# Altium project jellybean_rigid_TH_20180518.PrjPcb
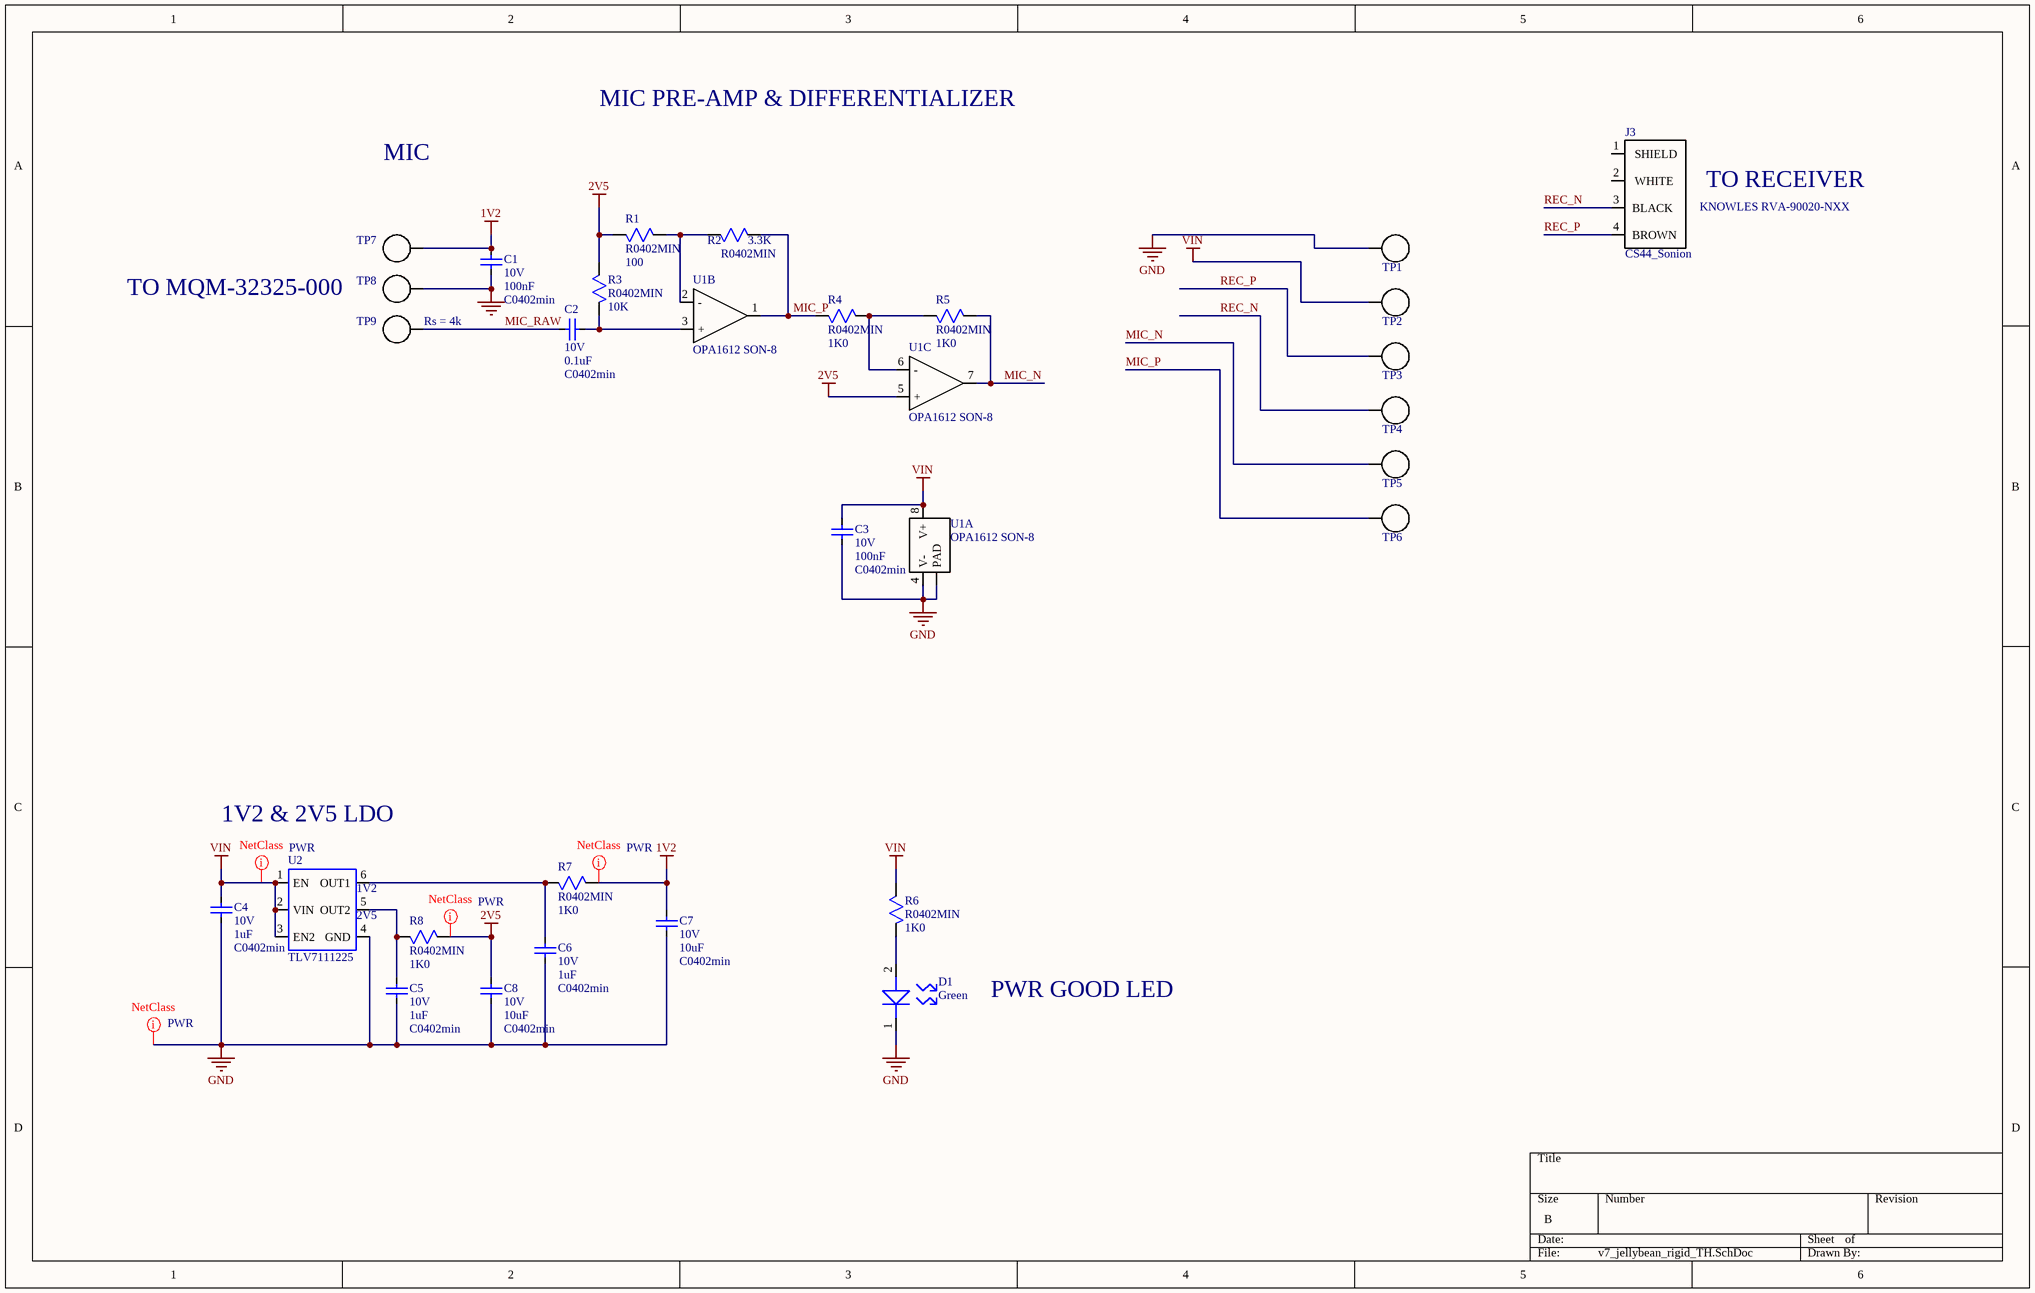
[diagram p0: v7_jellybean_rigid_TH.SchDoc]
1 sheet, 29 parts. Net scope: global (net labels, ports and power ports of the same name join across sheets).
Board file: v7_jellybean_rigid_TH.PcbDoc

## Sheet v7_jellybean_rigid_TH.SchDoc
size B

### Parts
C1  VoltageRating: 10V  [C0402min]  (hidden comment: 100nF)
C2  VoltageRating: 10V  [C0402min]  (hidden comment: 0.1uF)
C3  VoltageRating: 10V  [C0402min]  (hidden comment: 100nF)
C4  VoltageRating: 10V  [C0402min]  (hidden comment: 1uF)
C5  VoltageRating: 10V  [C0402min]  (hidden comment: 1uF)
C6  VoltageRating: 10V  [C0402min]  (hidden comment: 1uF)
C7  VoltageRating: 10V  [C0402min]  (hidden comment: 10uF)
C8  VoltageRating: 10V  [C0402min]  (hidden comment: 10uF)
D1  Color: Green  [LED0402min]  (hidden comment: LED, green)
J3  CS44_Sonion  [CS44_SOCKET_TH - EDGE - SONION]
R1  value 100  [R0402MIN]  (hidden comment: Resistor)
R2  value 3.3K  [R0402MIN]  (hidden comment: Resistor)
R3  value 10K  [R0402MIN]  (hidden comment: Resistor)
R4  value 1K0  [R0402MIN]  (hidden comment: Resistor)
R5  value 1K0  [R0402MIN]  (hidden comment: Resistor)
R6  value 1K0  [R0402MIN]  (hidden comment: Resistor)
R7  value 1K0  [R0402MIN]  (hidden comment: Resistor)
R8  value 1K0  [R0402MIN]  (hidden comment: Resistor)
TP1  Not A Part  [TP_32AWG]  (value not drawn)
TP2  Not A Part  [TP_32AWG]  (value not drawn)
TP3  Not A Part  [TP_32AWG]  (value not drawn)
TP4  Not A Part  [TP_32AWG]  (value not drawn)
TP5  Not A Part  [TP_32AWG]  (value not drawn)
TP6  Not A Part  [TP_32AWG]  (value not drawn)
TP7  Not A Part  [TP_32AWG]  (value not drawn)
TP8  Not A Part  [TP_32AWG]  (value not drawn)
TP9  Not A Part  [TP_32AWG]  (value not drawn)
U1  OPA1612 SON-8  [SON-8]  (parts A,B,C of 3)
U2  TLV7111225  [TLV711x]

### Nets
1V2: C1.1 C7.2 R7.2 TP7.1(MTG)
2V5: C8.1 R1.2 R3.2 R8.2 U1.5(+)
GND: C1.2 C3.1 C4.2 C5.2 C6.2 C7.1 C8.2 D1.1 TP1.1(MTG) TP8.1(MTG) U1.4(V-) U1.PAD U2.4(GND)
VIN: C3.2 C4.1 R6.2 TP2.1(MTG) U1.8(V+) U2.1(EN) U2.2(VIN) U2.3(EN2)
MIC_N: R5.2 TP5.1(MTG) U1.7
MIC_P: R2.2 R4.1 TP6.1(MTG) U1.1
MIC_RAW: C2.1 TP9.1(MTG)
REC_N: J3.3(BLACK) TP4.1(MTG)
REC_P: J3.4(BROWN) TP3.1(MTG)
NetC2_2: C2.2 R3.1 U1.3(+)
NetC5_1: C5.1 R8.1 U2.5(OUT2)
NetC6_1: C6.1 R7.1 U2.6(OUT1)
NetD1_2: D1.2 R6.1
NetR1_1: R1.1 R2.1 U1.2(-)
NetR4_2: R4.2 R5.1 U1.6(-)

Not connected (* = marked no-connect by the designer): J3 1(SHIELD) 2(WHITE)

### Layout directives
net class PWR: 1V2, 2V5, GND, VIN

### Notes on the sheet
- MIC
- MIC PRE-AMP & DIFFERENTIALIZER
- KNOWLES RVA-90020-NXX
- TO RECEIVER
- TO MQM-32325-000
- (near TP9) Rs = 4k
- 1V2 & 2V5 LDO
- PWR GOOD LED

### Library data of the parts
C1 C3 = CAP: Nonpolarized capacitor, SMD, 100nF, 0402, 10V, X5R; Manufacturer: Samsung; MfgPartNumber: CL05A104KP5NNNC
C2 C7 C8 = CAP: Nonpolarized capacitor, SMD, 10uF, 0402, 10V, X5R; Manufacturer: Samsung; MfgPartNumber: CL05A106MP8NUB8
C4-C6 = CAP: Nonpolarized capacitor, SMD, 1uF, 0402, 10V, X5R; Manufacturer: Samsung; MfgPartNumber: CL05A105MP5NNNC
D1 = LED: LED, SMD, green, clear, 0402; Manufacturer: SunLED; MfgPartNumber: XZVG68W-2
J3 = CS44_Sonion: 4-pin connector. Specify TH vs. SMD; Manufacturer: Knowles; MfgPartNumber: CS44
R1 = RES: Resistor, SMD, 100, 0402, 1%; Manufacturer: Yageo; MfgPartNumber: RC0402FR-07100RL
R2 R3 = RES: Resistor, SMD, 10K, 0402, 1%; Manufacturer: Yageo; MfgPartNumber: RC0402FR-0710KL
R4-R8 = RES: Resistor, SMD, 1K, 0402, 1%; Manufacturer: Yageo; MfgPartNumber: RC0402FR-071KL
TP1-TP9 = TP_32AWG: 0.305mm (12mil) hole for 32AWG wire. No BOM item.
U1 = OPA1612_SON-8: dual op-amp in SON-8 package; Manufacturer: TI; MfgPartNumber: OPA1612AIDRGR
U2 = TLV7111225: IC dual linear reg, 1V2+ 2V5, WSON-6; Manufacturer: TI; MfgPartNumber: TLV7111225DSER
